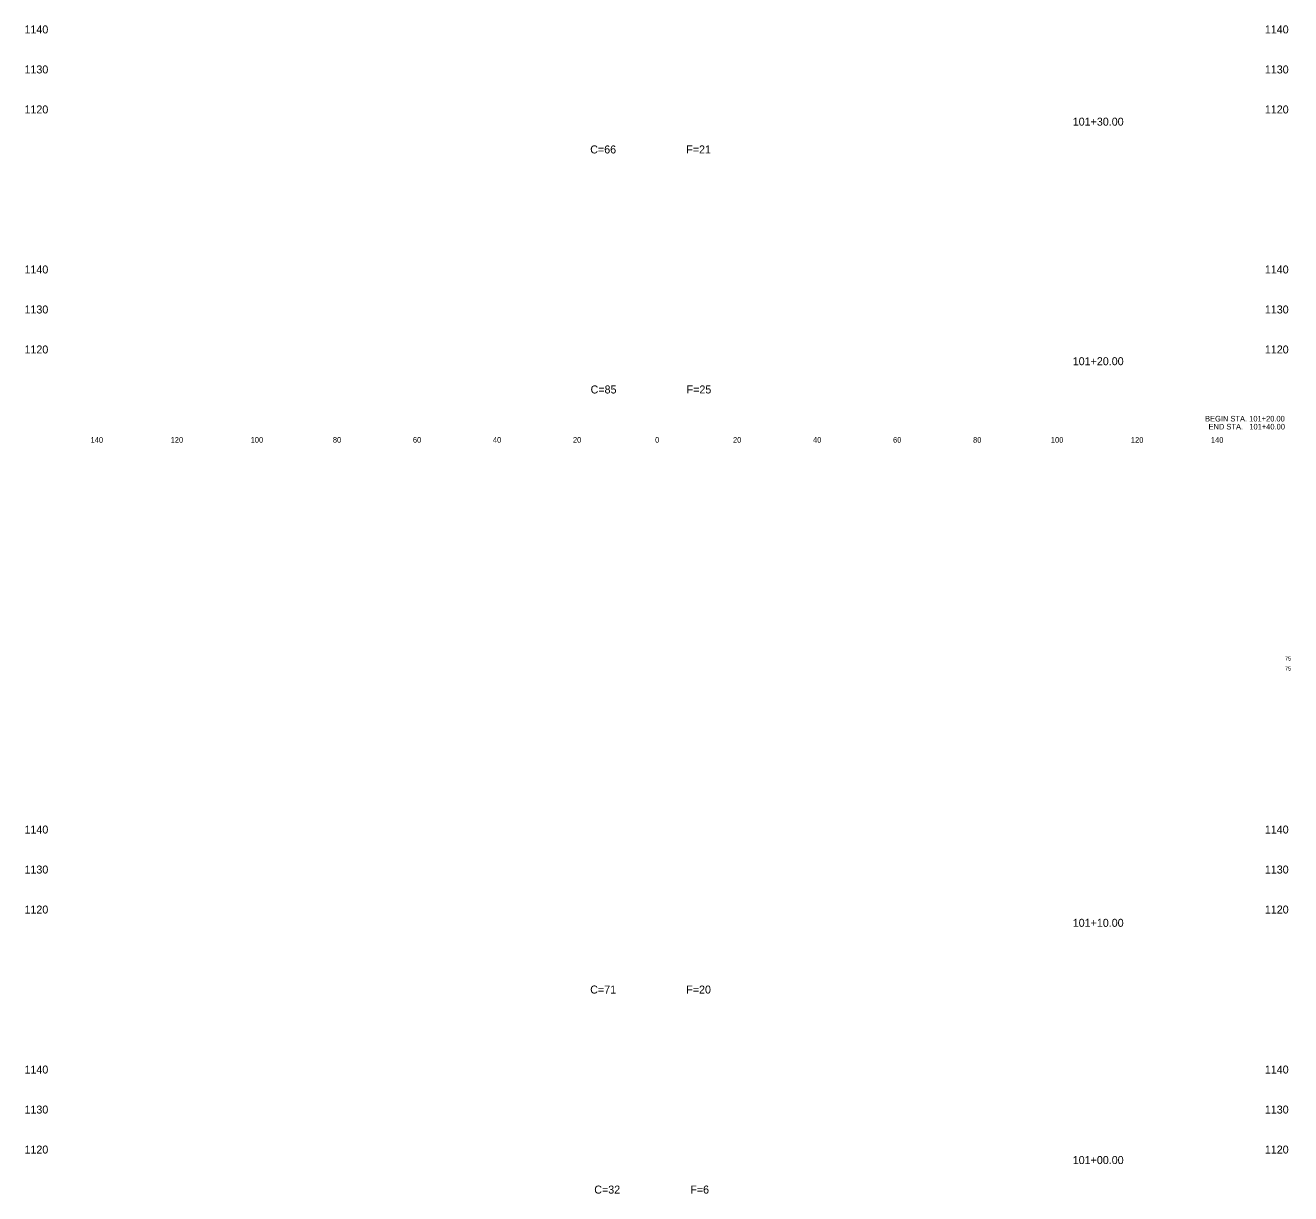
# Model space of a CAD drawing. Extents: x -200 to 1318, y -200 to 2244.
# Drawn here: x 1001.9 to 1318.2, y 1330 to 1622 of the extents above; entities that cross this region are included whole.
import ezdxf

# ---------------------------------------------------------------- set-up
doc = ezdxf.new("R2010")
doc.units = 0
for name, color, linetype in [('Default', 7, 'Continuous'), ('DESIGN - SHEET - Corner Text', 7, 'Continuous'), ('DESIGN - TYPICAL - Text', 7, 'Continuous')]:
    doc.layers.add(name, color=color, linetype=linetype)

msp = doc.modelspace()

# ---------------------------------------------------------------- texts
at = {"layer": 'Default'}
for s, height, p in [('     1140     ', 2, (998.01, 1620)), ('     1140     ', 2, (1308.01, 1620)), ('     1130     ', 2, (998.01, 1610)), ('     1130     ', 2, (1308.01, 1610)), ('     1120     ', 2, (998.01, 1600)), ('     1120     ', 2, (1308.01, 1600)), ('     101+30.00     ', 2, (1260, 1596.94)), ('     1140     ', 2, (998.01, 1560)), ('     1140     ', 2, (1308.01, 1560)), ('     1130     ', 2, (998.01, 1550)), ('     1130     ', 2, (1308.01, 1550)), ('     1120     ', 2, (998.01, 1540)), ('     1120     ', 2, (1308.01, 1540)), ('     101+20.00     ', 2, (1260, 1537.06)), ('     140     ', 1.4, (1015.65, 1517.7)), ('     120     ', 1.4, (1035.65, 1517.7)), ('     100     ', 1.4, (1055.65, 1517.7)), ('     80     ', 1.4, (1076.2, 1517.7)), ('     60     ', 1.4, (1096.2, 1517.7)), ('     40     ', 1.4, (1116.2, 1517.7)), ('     20     ', 1.4, (1136.2, 1517.7)), ('     0     ', 1.4, (1156.74, 1517.7)), ('     0     ', 1.4, (1156.74, 1517.7)), ('     20     ', 1.4, (1176.2, 1517.7)), ('     40     ', 1.4, (1196.2, 1517.7)), ('     60     ', 1.4, (1216.2, 1517.7)), ('     80     ', 1.4, (1236.2, 1517.7)), ('     100     ', 1.4, (1255.65, 1517.7)), ('     120     ', 1.4, (1275.65, 1517.7)), ('     140     ', 1.4, (1295.65, 1517.7)), ('     1140     ', 2, (998.01, 1420)), ('     1140     ', 2, (1308.01, 1420)), ('     1130     ', 2, (998.01, 1410)), ('     1130     ', 2, (1308.01, 1410)), ('     1120     ', 2, (998.01, 1400)), ('     1120     ', 2, (1308.01, 1400)), ('     101+10.00     ', 2, (1260, 1396.68)), ('     1140     ', 2, (998.01, 1360)), ('     1140     ', 2, (1308.01, 1360)), ('     1130     ', 2, (998.01, 1350)), ('     1130     ', 2, (1308.01, 1350)), ('     1120     ', 2, (998.01, 1340)), ('     1120     ', 2, (1308.01, 1340)), ('     101+00.00     ', 2, (1260, 1337.38))]:
    msp.add_text(s, height=height, dxfattribs=at).set_placement(p)
at = {"layer": 'DESIGN - SHEET - Corner Text'}
for s, height, p in [('BEGIN STA. 101+20.00', 1.4, (1296.78, 1523)), ('END STA.   101+40.00', 1.4, (1297.65, 1521)), ('75', 1, (1316.75, 1463.25)), ('75', 1, (1316.75, 1460.75))]:
    msp.add_text(s, height=height, dxfattribs=at).set_placement(p)
at = {"layer": 'DESIGN - TYPICAL - Text'}
for s, p in [('C=66', (1143.12, 1590)), ('F=21', (1167.12, 1590)), ('C=85', (1143.21, 1530)), ('F=25', (1167.21, 1530)), ('C=71', (1143.12, 1380)), ('F=20', (1167.12, 1380)), ('C=32', (1144.13, 1330)), ('F=6', (1168.13, 1330))]:
    msp.add_text(s, height=2, dxfattribs=at).set_placement(p)

doc.saveas('drawing.dxf')
